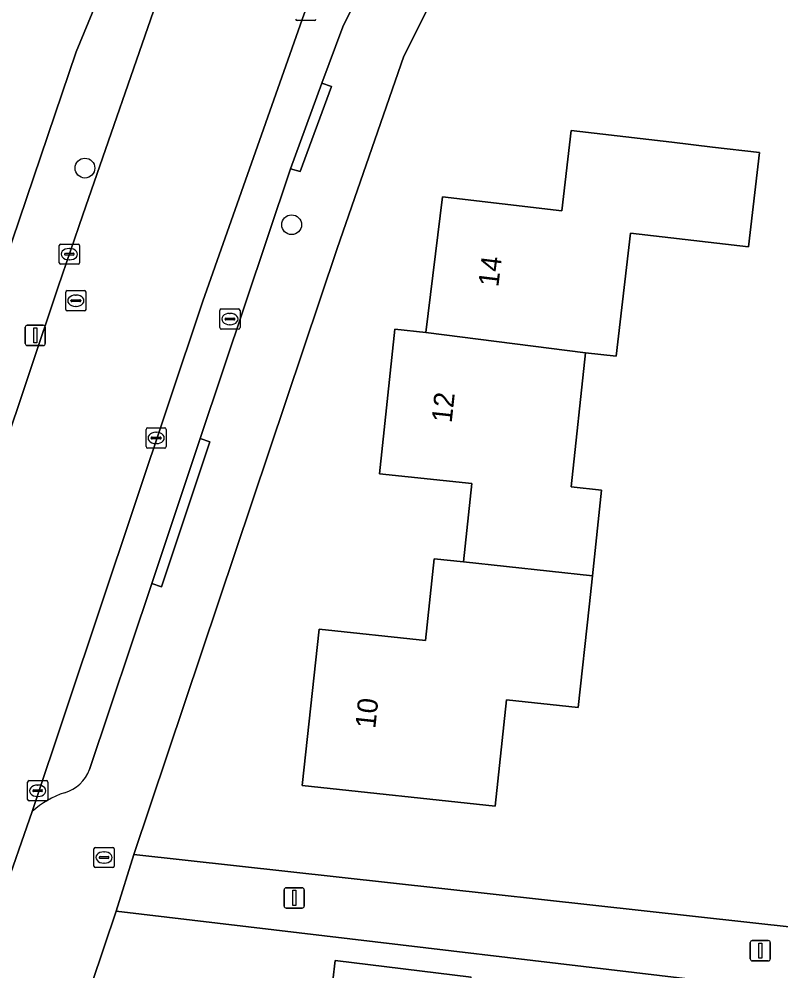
# Model space of a CAD drawing. Extents: x 162396 to 163643, y 386452 to 387406.
# Drawn here: x 162738.75 to 162776.34, y 386666.15 to 386713.11 of the extents above; entities that cross this region are included whole.
import ezdxf

# ---------------------------------------------------------------- set-up
doc = ezdxf.new("R2010")
doc.units = 0
for name, color, linetype in [('IMGEO_Boom', 7, 'Continuous'), ('IMGEO_Brandkraan', 7, 'Continuous'), ('IMGEO_Erf', 7, 'Continuous'), ('IMGEO_Kolk', 7, 'Continuous'), ('IMGEO_Lichtmast', 7, 'Continuous'), ('IMGEO_Pand', 7, 'Continuous'), ('IMGEO_Pand_nummerreeks', 7, 'Continuous'), ('IMGEO_Parkeervlak_open', 7, 'Continuous'), ('IMGEO_Rijbaan_lokaal_open', 7, 'Continuous'), ('IMGEO_Rioolput', 7, 'Continuous'), ('IMGEO_Voetpad_open', 7, 'Continuous')]:
    doc.layers.add(name, color=color, linetype=linetype)

msp = doc.modelspace()

# ---------------------------------------------------------------- linework, layer by layer
at = {"layer": 'IMGEO_Boom'}
for centre in [(162742.004, 386705.757), (162752.201, 386702.964)]:
    msp.add_circle(centre, 0.489, dxfattribs=at)
at = {"layer": 'IMGEO_Brandkraan'}
for p, q in [((162742.448, 386671.325), (162742.448, 386672.177)), ((162742.523, 386672.251), (162743.375, 386672.251)), ((162742.936, 386672.031), (162742.961, 386672.031)), ((162743.449, 386672.177), (162743.449, 386671.325)), ((162742.707, 386671.745), (162742.707, 386671.757)), ((162743.145, 386671.708), (162742.747, 386671.708)), ((162742.75, 386671.794), (162743.148, 386671.794)), ((162743.191, 386671.757), (162743.191, 386671.745)), ((162743.375, 386671.251), (162742.523, 386671.251)), ((162742.959, 386671.471), (162742.934, 386671.471))]:
    msp.add_line(p, q, dxfattribs=at)
for points in [[(162742.448, 386671.325), (162742.448, 386672.177)], [(162742.523, 386672.251), (162743.375, 386672.251)], [(162743.449, 386672.177), (162743.449, 386671.325)], [(162743.375, 386671.251), (162742.523, 386671.251)]]:
    msp.add_lwpolyline(points, dxfattribs=at)
for centre, radius, start, end in [((162742.525, 386672.175), 0.0765, 91.552, 178.448), ((162742.525, 386672.175), 0.0765, 91.552, 178.448), ((162743.373, 386672.175), 0.0765, 1.552, 88.448), ((162743.373, 386672.175), 0.0765, 1.552, 88.448), ((162742.747, 386671.754), 0.0403, 85.8775, 175.7526), ((162742.744, 386671.744), 0.0366, 178.938, 274.7102), ((162743.148, 386671.751), 0.043, 264.8664, 352.4533), ((162743.152, 386671.756), 0.0386, 1.7309, 96.639), ((162742.525, 386671.327), 0.0765, 181.552, 268.448), ((162742.525, 386671.327), 0.0765, 181.552, 268.448), ((162743.373, 386671.327), 0.0765, 271.552, 358.448), ((162743.373, 386671.327), 0.0765, 271.552, 358.448)]:
    msp.add_arc(centre, radius, start, end, dxfattribs=at)
for centre, major_axis, ratio, start_param, end_param in [((162742.935, 386671.751), (-0.387, 0.002), 0.722429, 4.712389, 7.853982), ((162742.96, 386671.751), (-0.39, 0.002), 0.717154, 1.570796, 4.712389)]:
    msp.add_ellipse(centre, major_axis=major_axis, ratio=ratio, start_param=start_param, end_param=end_param, dxfattribs=at)
at = {"layer": 'IMGEO_Erf'}
for points in [[(162776.93, 386743.582), (162768.744, 386730.951), (162762.934, 386721.672), (162757.742, 386711.279), (162754.454, 386701.785), (162744.409, 386671.894), (162782.247, 386667.715), (162783.774, 386663.035), (162787.296, 386663.004), (162855.09, 386662.415)], [(162708.666, 386672.324), (162727.566, 386670.164), (162741.576, 386711.487), (162744.257, 386717.994)], [(162786.017, 386651.238), (162777.902, 386652.152), (162779.378, 386664.867), (162743.548, 386669.105), (162731.458, 386633.225), (162730.396, 386627.558), (162729.703, 386622.29), (162729.171, 386615.834), (162728.3, 386607.457), (162728.244, 386606.221), (162728.319, 386605.252)], [(162753.996, 386663.718), (162754.353, 386666.665), (162761.065, 386665.852)]]:
    msp.add_lwpolyline(points, dxfattribs=at)
msp.add_lwpolyline([(162766.343, 386679.145), (162762.799, 386679.525), (162762.236, 386674.275), (162752.728, 386675.295), (162753.556, 386683.015), (162758.807, 386682.452), (162759.239, 386686.481), (162760.672, 386686.327), (162761.087, 386690.195), (162756.529, 386690.684), (162757.294, 386697.812), (162758.82, 386697.649), (162759.637, 386704.341), (162765.532, 386703.651), (162765.995, 386707.61), (162770.962, 386707.029), (162772.97, 386706.794), (162775.28, 386706.524), (162774.735, 386701.869), (162768.924, 386702.549), (162768.21, 386696.484), (162766.702, 386696.645), (162765.993, 386690.033), (162767.493, 386689.873), (162767.039, 386685.642), (162766.876, 386684.117)], close=True, dxfattribs=at)
at = {"layer": 'IMGEO_Kolk'}
for p, q in [((162753.321, 386713.036), (162752.469, 386713.036)), ((162740.81, 386702.012), (162741.662, 386702.012)), ((162740.735, 386701.086), (162740.735, 386701.938)), ((162741.037, 386701.555), (162741.435, 386701.555)), ((162741.223, 386701.792), (162741.248, 386701.792)), ((162741.736, 386701.938), (162741.736, 386701.086)), ((162740.994, 386701.506), (162740.994, 386701.518)), ((162741.432, 386701.469), (162741.034, 386701.469)), ((162741.246, 386701.232), (162741.221, 386701.232)), ((162741.478, 386701.518), (162741.478, 386701.506)), ((162741.662, 386701.012), (162740.81, 386701.012)), ((162745.017, 386692.018), (162745.017, 386692.87)), ((162745.092, 386692.944), (162745.944, 386692.944)), ((162745.505, 386692.724), (162745.53, 386692.724)), ((162746.018, 386692.87), (162746.018, 386692.018)), ((162745.276, 386692.438), (162745.276, 386692.45)), ((162745.714, 386692.401), (162745.316, 386692.401)), ((162745.319, 386692.487), (162745.717, 386692.487)), ((162745.528, 386692.164), (162745.503, 386692.164)), ((162745.76, 386692.45), (162745.76, 386692.438)), ((162745.944, 386691.944), (162745.092, 386691.944)), ((162739.175, 386674.615), (162739.175, 386675.467)), ((162739.25, 386675.541), (162740.102, 386675.541)), ((162739.663, 386675.321), (162739.688, 386675.321)), ((162740.176, 386675.467), (162740.176, 386674.615)), ((162739.434, 386675.035), (162739.434, 386675.047)), ((162739.872, 386674.998), (162739.474, 386674.998)), ((162739.477, 386675.084), (162739.875, 386675.084)), ((162739.918, 386675.047), (162739.918, 386675.035)), ((162740.102, 386674.541), (162739.25, 386674.541)), ((162739.686, 386674.761), (162739.661, 386674.761))]:
    msp.add_line(p, q, dxfattribs=at)
for points in [[(162753.321, 386713.036), (162752.469, 386713.036)], [(162740.81, 386702.012), (162741.662, 386702.012)], [(162740.735, 386701.086), (162740.735, 386701.938)], [(162741.736, 386701.938), (162741.736, 386701.086)], [(162741.662, 386701.012), (162740.81, 386701.012)], [(162745.017, 386692.018), (162745.017, 386692.87)], [(162745.092, 386692.944), (162745.944, 386692.944)], [(162746.018, 386692.87), (162746.018, 386692.018)], [(162745.944, 386691.944), (162745.092, 386691.944)], [(162739.175, 386674.615), (162739.175, 386675.467)], [(162739.25, 386675.541), (162740.102, 386675.541)], [(162740.176, 386675.467), (162740.176, 386674.615)], [(162740.102, 386674.541), (162739.25, 386674.541)]]:
    msp.add_lwpolyline(points, dxfattribs=at)
for centre, radius, start, end in [((162752.471, 386713.112), 0.0765, 181.552, 268.448), ((162752.471, 386713.112), 0.0765, 181.552, 268.448), ((162753.319, 386713.112), 0.0765, 271.552, 358.448), ((162753.319, 386713.112), 0.0765, 271.552, 358.448), ((162740.812, 386701.936), 0.0765, 91.552, 178.448), ((162740.812, 386701.936), 0.0765, 91.552, 178.448), ((162741.66, 386701.936), 0.0765, 1.552, 88.448), ((162741.66, 386701.936), 0.0765, 1.552, 88.448), ((162741.034, 386701.515), 0.0403, 85.8775, 175.7526), ((162741.439, 386701.517), 0.0386, 1.7309, 96.639), ((162740.812, 386701.088), 0.0765, 181.552, 268.448), ((162740.812, 386701.088), 0.0765, 181.552, 268.448), ((162741.031, 386701.505), 0.0366, 178.938, 274.7102), ((162741.435, 386701.512), 0.043, 264.8664, 352.4533), ((162741.66, 386701.088), 0.0765, 271.552, 358.448), ((162741.66, 386701.088), 0.0765, 271.552, 358.448), ((162745.094, 386692.868), 0.0765, 91.552, 178.448), ((162745.094, 386692.868), 0.0765, 91.552, 178.448), ((162745.942, 386692.868), 0.0765, 1.552, 88.448), ((162745.942, 386692.868), 0.0765, 1.552, 88.448), ((162745.316, 386692.447), 0.0403, 85.8775, 175.7526), ((162745.313, 386692.437), 0.0366, 178.938, 274.7102), ((162745.717, 386692.444), 0.043, 264.8664, 352.4533), ((162745.721, 386692.449), 0.0386, 1.7309, 96.639), ((162745.094, 386692.02), 0.0765, 181.552, 268.448), ((162745.094, 386692.02), 0.0765, 181.552, 268.448), ((162745.942, 386692.02), 0.0765, 271.552, 358.448), ((162745.942, 386692.02), 0.0765, 271.552, 358.448), ((162739.252, 386675.465), 0.0765, 91.552, 178.448), ((162739.252, 386675.465), 0.0765, 91.552, 178.448), ((162740.1, 386675.465), 0.0765, 1.552, 88.448), ((162740.1, 386675.465), 0.0765, 1.552, 88.448), ((162739.474, 386675.044), 0.0403, 85.8775, 175.7526), ((162739.471, 386675.034), 0.0366, 178.938, 274.7102), ((162739.875, 386675.041), 0.043, 264.8664, 352.4533), ((162739.879, 386675.046), 0.0386, 1.7309, 96.639), ((162739.252, 386674.617), 0.0765, 181.552, 268.448), ((162739.252, 386674.617), 0.0765, 181.552, 268.448), ((162740.1, 386674.617), 0.0765, 271.552, 358.448), ((162740.1, 386674.617), 0.0765, 271.552, 358.448)]:
    msp.add_arc(centre, radius, start, end, dxfattribs=at)
for centre, major_axis, ratio, start_param, end_param in [((162741.222, 386701.512), (-0.387, 0.002), 0.722429, 4.712389, 7.853982), ((162741.247, 386701.512), (-0.39, 0.002), 0.717154, 1.570796, 4.712389), ((162745.504, 386692.444), (-0.387, 0.002), 0.722429, 4.712389, 7.853982), ((162745.529, 386692.444), (-0.39, 0.002), 0.717154, 1.570796, 4.712389), ((162739.662, 386675.041), (-0.387, 0.002), 0.722429, 4.712389, 7.853982), ((162739.687, 386675.041), (-0.39, 0.002), 0.717154, 1.570796, 4.712389)]:
    msp.add_ellipse(centre, major_axis=major_axis, ratio=ratio, start_param=start_param, end_param=end_param, dxfattribs=at)
at = {"layer": 'IMGEO_Lichtmast'}
for p, q in [((162739.06, 386697.106), (162739.06, 386697.906)), ((162739.06, 386697.906), (162739.06, 386697.106)), ((162739.16, 386698.006), (162739.95, 386698.006)), ((162739.95, 386698.006), (162739.16, 386698.006)), ((162740.05, 386697.906), (162740.05, 386697.106)), ((162740.05, 386697.106), (162740.05, 386697.906)), ((162739.95, 386697.006), (162739.16, 386697.006)), ((162739.16, 386697.006), (162739.95, 386697.006)), ((162751.832, 386669.356), (162751.832, 386670.156)), ((162751.832, 386670.156), (162751.832, 386669.356)), ((162751.932, 386670.256), (162752.722, 386670.256)), ((162752.722, 386670.256), (162751.932, 386670.256)), ((162752.822, 386670.156), (162752.822, 386669.356)), ((162752.822, 386669.356), (162752.822, 386670.156)), ((162752.722, 386669.256), (162751.932, 386669.256)), ((162751.932, 386669.256), (162752.722, 386669.256)), ((162774.824, 386666.753), (162774.824, 386667.553)), ((162774.824, 386667.553), (162774.824, 386666.753)), ((162774.924, 386667.653), (162775.714, 386667.653)), ((162775.714, 386667.653), (162774.924, 386667.653)), ((162775.814, 386667.553), (162775.814, 386666.753)), ((162775.814, 386666.753), (162775.814, 386667.553)), ((162775.714, 386666.653), (162774.924, 386666.653)), ((162774.924, 386666.653), (162775.714, 386666.653))]:
    msp.add_line(p, q, dxfattribs=at)
for points in [[(162739.48, 386697.881), (162739.63, 386697.881), (162739.63, 386697.131), (162739.48, 386697.131), (162739.48, 386697.881)], [(162752.252, 386670.131), (162752.402, 386670.131), (162752.402, 386669.381), (162752.252, 386669.381), (162752.252, 386670.131)], [(162775.244, 386667.528), (162775.394, 386667.528), (162775.394, 386666.778), (162775.244, 386666.778), (162775.244, 386667.528)]]:
    msp.add_lwpolyline(points, dxfattribs=at)
for centre, start, end in [((162739.16, 386697.906), 90, 180), ((162739.16, 386697.906), 90, 180), ((162739.95, 386697.906), 0, 90), ((162739.95, 386697.906), 360, 90), ((162739.16, 386697.106), 180, 270), ((162739.16, 386697.106), 180, 270), ((162739.95, 386697.106), 270, 0), ((162739.95, 386697.106), 270, 0), ((162751.932, 386670.156), 90, 180), ((162751.932, 386670.156), 90, 180), ((162752.722, 386670.156), 0, 90), ((162752.722, 386670.156), 360, 90), ((162751.932, 386669.356), 180, 270), ((162751.932, 386669.356), 180, 270), ((162752.722, 386669.356), 270, 0), ((162752.722, 386669.356), 270, 0), ((162774.924, 386667.553), 90, 180), ((162774.924, 386667.553), 90, 180), ((162775.714, 386667.553), 0, 90), ((162775.714, 386667.553), 360, 90), ((162774.924, 386666.753), 180, 270), ((162774.924, 386666.753), 180, 270), ((162775.714, 386666.753), 270, 0), ((162775.714, 386666.753), 270, 0)]:
    msp.add_arc(centre, 0.1, start, end, dxfattribs=at)
at = {"layer": 'IMGEO_Pand'}
for points in [[(162775.28, 386706.524), (162772.97, 386706.794), (162770.962, 386707.029), (162765.995, 386707.61), (162765.532, 386703.651), (162759.637, 386704.341), (162758.82, 386697.649), (162766.702, 386696.645), (162768.21, 386696.484), (162768.924, 386702.549), (162774.735, 386701.869)], [(162758.82, 386697.649), (162757.294, 386697.812), (162756.529, 386690.684), (162761.087, 386690.195), (162760.672, 386686.327), (162767.039, 386685.642), (162767.493, 386689.873), (162765.993, 386690.033), (162766.702, 386696.645)], [(162760.672, 386686.327), (162759.239, 386686.481), (162758.807, 386682.452), (162753.556, 386683.015), (162752.728, 386675.295), (162762.236, 386674.275), (162762.799, 386679.525), (162766.343, 386679.145), (162766.876, 386684.117), (162767.039, 386685.642)], [(162756.388, 386661.108), (162760.431, 386660.618), (162760.464, 386660.889), (162761.065, 386665.852), (162754.353, 386666.665), (162753.996, 386663.718), (162749.378, 386664.277), (162746.25, 386664.656), (162745.137, 386655.465), (162749.406, 386654.948), (162749.86, 386654.893), (162749.532, 386652.189), (162749.632, 386652.177), (162751.662, 386651.939), (162751.979, 386654.636), (162755.552, 386654.203)]]:
    msp.add_lwpolyline(points, close=True, dxfattribs=at)
at = {"layer": 'IMGEO_Parkeervlak_open'}
for points in [[(162769.561, 386742.426), (162767.447, 386739.091), (162760.497, 386728.254), (162756.44, 386721.247), (162752.818, 386713.374), (162747.82, 386699.195), (162739.403, 386674.014)], [(162742.231, 386676.09), (162745.3, 386685.267), (162747.69, 386692.411), (162752.14, 386705.717), (162753.698, 386709.944), (162754.722, 386712.724), (162758.738, 386720.921), (162759.898, 386723.289), (162760.841, 386724.833), (162765.954, 386732.907), (162769.217, 386738.029)]]:
    msp.add_lwpolyline(points, dxfattribs=at)
for centre, radius, start, end in [((162740.489, 386676.724), 1.854, 286.0983, 339.995), ((162742.27, 386670.918), 4.22, 107.4774, 132.8037)]:
    msp.add_arc(centre, radius, start, end, dxfattribs=at)
at = {"layer": 'IMGEO_Rijbaan_lokaal_open'}
for points in [[(162820.766, 386835.256), (162768.682, 386753.831), (162766.226, 386750), (162764.605, 386747.471), (162755.937, 386733.921), (162751.779, 386727.044), (162747.378, 386718.341), (162745.663, 386714.324), (162741.907, 386703.446), (162740.68, 386699.903), (162730.769, 386670.321), (162730.673, 386670.035), (162728.857, 386664.611)], [(162726.599, 386636.073), (162727.35, 386638.325), (162728.125, 386640.647), (162729.554, 386644.862), (162730.39, 386647.436), (162731.37, 386650.353), (162732.546, 386653.782), (162733.829, 386657.575), (162736.244, 386664.738), (162736.362, 386665.025), (162737.942, 386669.81), (162739.403, 386674.014), (162747.82, 386699.195), (162752.818, 386713.374), (162756.44, 386721.247), (162760.497, 386728.254), (162767.447, 386739.091), (162769.561, 386742.426), (162771.413, 386745.192), (162780.364, 386759.153), (162780.603, 386759.42), (162809.431, 386804.415)]]:
    msp.add_lwpolyline(points, dxfattribs=at)
at = {"layer": 'IMGEO_Rioolput'}
for p, q in [((162741.13, 386699.715), (162741.982, 386699.715)), ((162741.055, 386698.789), (162741.055, 386699.641)), ((162741.314, 386699.209), (162741.314, 386699.221)), ((162741.357, 386699.258), (162741.755, 386699.258)), ((162741.543, 386699.495), (162741.568, 386699.495)), ((162741.798, 386699.221), (162741.798, 386699.209)), ((162742.056, 386699.641), (162742.056, 386698.789)), ((162741.982, 386698.715), (162741.13, 386698.715)), ((162741.752, 386699.172), (162741.354, 386699.172)), ((162741.566, 386698.935), (162741.541, 386698.935)), ((162748.655, 386697.886), (162748.655, 386698.738)), ((162748.73, 386698.812), (162749.582, 386698.812)), ((162749.656, 386698.738), (162749.656, 386697.886)), ((162748.914, 386698.306), (162748.914, 386698.318)), ((162749.352, 386698.269), (162748.954, 386698.269)), ((162748.957, 386698.355), (162749.355, 386698.355)), ((162749.143, 386698.592), (162749.168, 386698.592)), ((162749.398, 386698.318), (162749.398, 386698.306)), ((162749.582, 386697.812), (162748.73, 386697.812)), ((162749.166, 386698.032), (162749.141, 386698.032))]:
    msp.add_line(p, q, dxfattribs=at)
for points in [[(162741.13, 386699.715), (162741.982, 386699.715)], [(162741.055, 386698.789), (162741.055, 386699.641)], [(162742.056, 386699.641), (162742.056, 386698.789)], [(162741.982, 386698.715), (162741.13, 386698.715)], [(162748.655, 386697.886), (162748.655, 386698.738)], [(162748.73, 386698.812), (162749.582, 386698.812)], [(162749.656, 386698.738), (162749.656, 386697.886)], [(162749.582, 386697.812), (162748.73, 386697.812)]]:
    msp.add_lwpolyline(points, dxfattribs=at)
for centre, radius, start, end in [((162741.132, 386699.639), 0.0765, 91.552, 178.448), ((162741.132, 386699.639), 0.0765, 91.552, 178.448), ((162741.98, 386699.639), 0.0765, 1.552, 88.448), ((162741.98, 386699.639), 0.0765, 1.552, 88.448), ((162741.354, 386699.218), 0.0403, 85.8775, 175.7526), ((162741.351, 386699.208), 0.0366, 178.938, 274.7102), ((162741.755, 386699.215), 0.043, 264.8664, 352.4533), ((162741.759, 386699.22), 0.0386, 1.7309, 96.639), ((162741.132, 386698.791), 0.0765, 181.552, 268.448), ((162741.132, 386698.791), 0.0765, 181.552, 268.448), ((162741.98, 386698.791), 0.0765, 271.552, 358.448), ((162741.98, 386698.791), 0.0765, 271.552, 358.448), ((162748.732, 386698.736), 0.0765, 91.552, 178.448), ((162748.732, 386698.736), 0.0765, 91.552, 178.448), ((162749.58, 386698.736), 0.0765, 1.552, 88.448), ((162749.58, 386698.736), 0.0765, 1.552, 88.448), ((162748.954, 386698.315), 0.0403, 85.8775, 175.7526), ((162748.951, 386698.305), 0.0366, 178.938, 274.7102), ((162749.355, 386698.312), 0.043, 264.8664, 352.4533), ((162749.359, 386698.317), 0.0386, 1.7309, 96.639), ((162748.732, 386697.888), 0.0765, 181.552, 268.448), ((162748.732, 386697.888), 0.0765, 181.552, 268.448), ((162749.58, 386697.888), 0.0765, 271.552, 358.448), ((162749.58, 386697.888), 0.0765, 271.552, 358.448)]:
    msp.add_arc(centre, radius, start, end, dxfattribs=at)
for centre, major_axis, ratio, start_param, end_param in [((162741.542, 386699.215), (-0.387, 0.002), 0.722429, 4.712389, 7.853982), ((162741.567, 386699.215), (-0.39, 0.002), 0.717154, 1.570796, 4.712389), ((162749.142, 386698.312), (-0.387, 0.002), 0.722429, 4.712389, 7.853982), ((162749.167, 386698.312), (-0.39, 0.002), 0.717154, 1.570796, 4.712389)]:
    msp.add_ellipse(centre, major_axis=major_axis, ratio=ratio, start_param=start_param, end_param=end_param, dxfattribs=at)
at = {"layer": 'IMGEO_Voetpad_open'}
for points in [[(162821.929, 386842.61), (162820.19, 386839.921), (162819.797, 386839.145), (162811.483, 386826.237), (162810.358, 386824.421), (162809.763, 386823.512), (162804.178, 386814.988), (162802.507, 386812.457), (162766.009, 386755.197), (162762.683, 386750), (162762.044, 386749.001), (162752.537, 386734.127), (162746.835, 386723.64), (162744.257, 386717.994), (162741.576, 386711.487), (162727.566, 386670.164), (162725.964, 386665.516), (162718.999, 386644.672), (162717.288, 386638.674), (162716.12, 386632.546), (162715.541, 386626.964), (162715.359, 386624.084), (162714.566, 386612.643)], [(162727.85, 386664.953), (162728.745, 386667.616), (162729.661, 386670.376), (162730.673, 386670.035), (162730.769, 386670.321), (162740.68, 386699.903), (162741.907, 386703.446), (162745.663, 386714.324), (162747.378, 386718.341), (162751.779, 386727.044), (162755.937, 386733.921), (162764.605, 386747.471), (162764.184, 386747.74), (162765.63, 386750), (162768.256, 386754.104), (162768.682, 386753.831), (162820.766, 386835.256)], [(162754.454, 386701.785), (162757.742, 386711.279), (162762.934, 386721.672), (162768.744, 386730.951), (162776.93, 386743.582), (162779.146, 386747.164), (162778.517, 386747.471)], [(162769.217, 386738.029), (162765.954, 386732.907), (162760.841, 386724.833), (162761.28, 386724.597), (162759.183, 386720.695), (162758.738, 386720.921), (162754.722, 386712.724), (162753.698, 386709.944), (162754.169, 386709.782), (162752.624, 386705.589), (162752.14, 386705.717), (162747.69, 386692.411), (162748.162, 386692.251), (162745.773, 386685.107), (162745.3, 386685.267), (162742.231, 386676.09)], [(162728.319, 386605.252), (162728.244, 386606.221), (162728.3, 386607.457), (162729.171, 386615.834), (162729.703, 386622.29), (162730.396, 386627.558), (162731.458, 386633.225), (162743.548, 386669.105), (162744.409, 386671.894), (162754.454, 386701.785)], [(162739.403, 386674.014), (162737.942, 386669.81), (162736.362, 386665.025)]]:
    msp.add_lwpolyline(points, dxfattribs=at)
for points in [[(162753.698, 386709.944), (162752.14, 386705.717), (162752.624, 386705.589), (162754.169, 386709.782)], [(162747.69, 386692.411), (162745.3, 386685.267), (162745.773, 386685.107), (162748.162, 386692.251)], [(162782.247, 386667.715), (162744.409, 386671.894), (162743.548, 386669.105), (162779.378, 386664.867), (162777.902, 386652.152), (162786.017, 386651.238), (162787.296, 386663.004), (162783.774, 386663.035)]]:
    msp.add_lwpolyline(points, close=True, dxfattribs=at)
for centre, radius, start, end in [((162740.489, 386676.724), 1.854, 286.0983, 339.995), ((162742.27, 386670.918), 4.22, 107.4774, 132.8037)]:
    msp.add_arc(centre, radius, start, end, dxfattribs=at)

# ---------------------------------------------------------------- texts
at = {"layer": 'IMGEO_Pand_nummerreeks'}
for s, rotation, p in [('14', 83.0388, (162762.395, 386699.868)), ('12', 83.8743, (162760.094, 386693.165)), ('10', 83.8782, (162756.325, 386678.078))]:
    msp.add_text(s, height=1, rotation=rotation, dxfattribs=at).set_placement(p)

doc.saveas('drawing.dxf')
